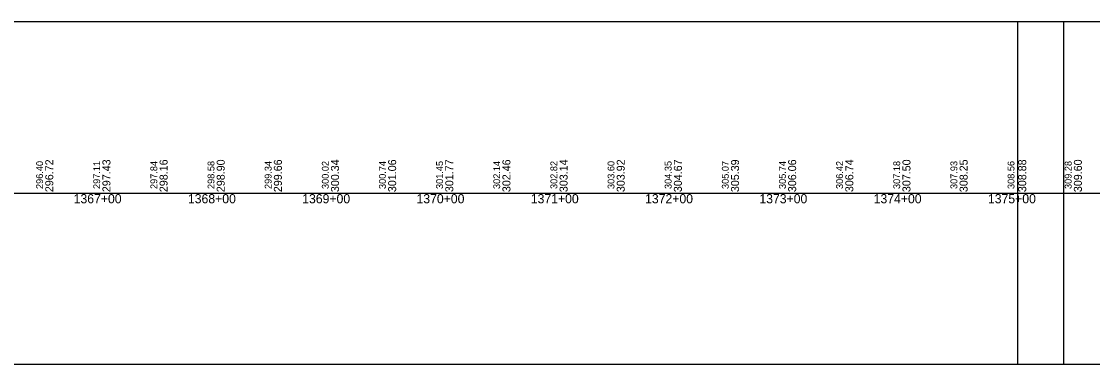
# Model space of a CAD drawing. Extents: x 2898 to 49495, y -15038 to -13538.
# Drawn here: x 26083 to 27021, y -15038 to -14738 of the extents above; entities that cross this region are included whole.
import ezdxf

# ---------------------------------------------------------------- set-up
doc = ezdxf.new("R2010")
doc.units = 0
for name, color, linetype in [('RD_DDB_StaTX', 7, 'Continuous'), ('RD_DDB_StripGrade', 7, 'Continuous'), ('RD_GPK_Profile_Cell', 7, 'Continuous'), ('RD_SHT_ShtClip', 7, 'Continuous')]:
    doc.layers.add(name, color=color, linetype=linetype)

msp = doc.modelspace()

# ---------------------------------------------------------------- linework, layer by layer
at = {"layer": 'RD_GPK_Profile_Cell'}
msp.add_line((2976.05, -14888.47), (48721.13, -14888.47), dxfattribs=at)
at = {"layer": 'RD_SHT_ShtClip'}
for points in [[(25455.38, -14738.47), (26995.38, -14738.47), (26995.38, -15038.47), (25455.38, -15038.47)], [(26955.38, -14738.47), (28495.38, -14738.47), (28495.38, -15038.47), (26955.38, -15038.47)]]:
    msp.add_lwpolyline(points, close=True, dxfattribs=at)

# ---------------------------------------------------------------- texts
at = {"layer": 'RD_DDB_StaTX'}
for s, p in [('1367+00', (26129.18, -14897.47)), ('1368+00', (26229.18, -14897.47)), ('1369+00', (26329.18, -14897.47)), ('1370+00', (26429.18, -14897.47)), ('1371+00', (26529.18, -14897.47)), ('1372+00', (26629.18, -14897.47)), ('1373+00', (26729.18, -14897.47)), ('1374+00', (26829.18, -14897.47)), ('1375+00', (26929.18, -14897.47))]:
    msp.add_text(s, height=8, dxfattribs=at).set_placement(p)
at = {"layer": 'RD_DDB_StripGrade'}
for s, height, p in [('296.40', 6, (26102.38, -14884.98)), ('296.72', 7, (26111.38, -14887.72)), ('297.11', 6, (26152.38, -14884.98)), ('297.43', 7, (26161.38, -14887.72)), ('297.84', 6, (26202.38, -14884.98)), ('298.16', 7, (26211.38, -14887.72)), ('298.58', 6, (26252.38, -14884.98)), ('298.90', 7, (26261.38, -14887.72)), ('299.34', 6, (26302.38, -14884.98)), ('299.66', 7, (26311.38, -14887.72)), ('300.02', 6, (26352.38, -14884.98)), ('300.34', 7, (26361.38, -14887.72)), ('300.74', 6, (26402.38, -14884.98)), ('301.06', 7, (26411.38, -14887.72)), ('301.45', 6, (26452.38, -14884.98)), ('301.77', 7, (26461.38, -14887.72)), ('302.14', 6, (26502.38, -14884.98)), ('302.46', 7, (26511.38, -14887.72)), ('302.82', 6, (26552.38, -14884.98)), ('303.14', 7, (26561.38, -14887.72)), ('303.60', 6, (26602.38, -14884.98)), ('303.92', 7, (26611.38, -14887.72)), ('304.35', 6, (26652.38, -14884.98)), ('304.67', 7, (26661.38, -14887.72)), ('305.07', 6, (26702.38, -14884.98)), ('305.39', 7, (26711.38, -14887.72)), ('305.74', 6, (26752.38, -14884.98)), ('306.06', 7, (26761.38, -14887.72)), ('306.42', 6, (26802.38, -14884.98)), ('306.74', 7, (26811.38, -14887.72)), ('307.18', 6, (26852.38, -14884.98)), ('307.50', 7, (26861.38, -14887.72)), ('307.93', 6, (26902.38, -14884.98)), ('308.25', 7, (26911.38, -14887.72)), ('308.56', 6, (26952.38, -14884.98)), ('308.88', 7, (26962.68, -14887.72)), ('309.28', 6, (27002.38, -14884.98)), ('309.60', 7, (27011.38, -14887.72))]:
    msp.add_text(s, height=height, rotation=90, dxfattribs=at).set_placement(p)

doc.saveas('drawing.dxf')
